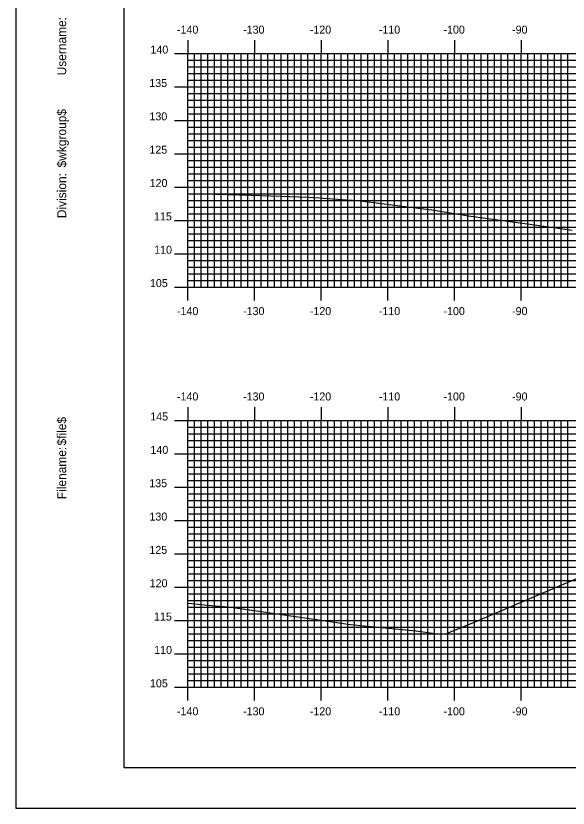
# Model space of a CAD drawing. Extents: x 852147 to 852490, y 364661 to 364881.
# Drawn here: x 852147 to 852229.8, y 364661.3 to 364780 of the extents above; entities that cross this region are included whole.
import ezdxf

# ---------------------------------------------------------------- set-up
doc = ezdxf.new("R2010")
doc.units = 0
for name, color, linetype in [('BORDER', 7, 'Continuous'), ('H_V ANNOTATION', 7, 'Continuous'), ('MAJOR', 7, 'Continuous'), ('MINOR', 7, 'Continuous'), ('PLOT BOUNDARY', 7, 'Continuous'), ('S_Roadway_Centerline', 7, 'Continuous')]:
    doc.layers.add(name, color=color, linetype=linetype)

msp = doc.modelspace()

# ---------------------------------------------------------------- linework, layer by layer
at = {"layer": 'BORDER'}
msp.add_lwpolyline([(852163.16, 364667.37), (852483.16, 364667.37), (852483.16, 364877.37), (852163.16, 364877.37)], close=True, dxfattribs=at)
at = {"layer": 'MAJOR'}
for p, q in [((852172.76, 364776.37), (852172.76, 364774.37)), ((852182.76, 364776.37), (852182.76, 364774.37)), ((852192.76, 364776.37), (852192.76, 364774.37)), ((852202.76, 364776.37), (852202.76, 364774.37)), ((852212.76, 364776.37), (852212.76, 364774.37)), ((852222.76, 364776.37), (852222.76, 364774.37)), ((852170.75, 364774.37), (852172.76, 364774.37)), ((852172.76, 364774.37), (852452.76, 364774.37)), ((852172.76, 364739.37), (852172.76, 364774.37)), ((852172.76, 364739.37), (852172.76, 364774.37)), ((852172.76, 364774.37), (852452.76, 364774.37)), ((852182.76, 364739.37), (852182.76, 364774.37)), ((852192.76, 364739.37), (852192.76, 364774.37)), ((852202.76, 364739.37), (852202.76, 364774.37)), ((852212.76, 364739.37), (852212.76, 364774.37)), ((852222.76, 364739.37), (852222.76, 364774.37)), ((852170.75, 364769.37), (852172.76, 364769.37)), ((852172.76, 364769.37), (852452.76, 364769.37)), ((852170.75, 364764.37), (852172.76, 364764.37)), ((852172.76, 364764.37), (852452.76, 364764.37)), ((852170.75, 364759.37), (852172.76, 364759.37)), ((852172.76, 364759.37), (852452.76, 364759.37)), ((852170.75, 364754.37), (852172.76, 364754.37)), ((852172.76, 364754.37), (852452.76, 364754.37)), ((852170.75, 364749.37), (852172.76, 364749.37)), ((852172.76, 364749.37), (852452.76, 364749.37)), ((852170.75, 364744.37), (852172.76, 364744.37)), ((852172.76, 364744.37), (852452.76, 364744.37)), ((852170.75, 364739.37), (852172.76, 364739.37)), ((852172.76, 364739.37), (852452.76, 364739.37)), ((852172.76, 364739.37), (852452.76, 364739.37)), ((852172.76, 364737.37), (852172.76, 364739.37)), ((852182.76, 364737.37), (852182.76, 364739.37)), ((852192.76, 364737.37), (852192.76, 364739.37)), ((852202.76, 364737.37), (852202.76, 364739.37)), ((852212.76, 364737.37), (852212.76, 364739.37)), ((852222.76, 364737.37), (852222.76, 364739.37)), ((852172.76, 364721.37), (852172.76, 364719.37)), ((852182.76, 364721.37), (852182.76, 364719.37)), ((852192.76, 364721.37), (852192.76, 364719.37)), ((852202.76, 364721.37), (852202.76, 364719.37)), ((852212.76, 364721.37), (852212.76, 364719.37)), ((852222.76, 364721.37), (852222.76, 364719.37)), ((852170.75, 364719.37), (852172.76, 364719.37)), ((852172.76, 364719.37), (852452.76, 364719.37)), ((852172.76, 364679.37), (852172.76, 364719.37)), ((852172.76, 364679.37), (852172.76, 364719.37)), ((852172.76, 364719.37), (852452.76, 364719.37)), ((852182.76, 364679.37), (852182.76, 364719.37)), ((852192.76, 364679.37), (852192.76, 364719.37)), ((852202.76, 364679.37), (852202.76, 364719.37)), ((852212.76, 364679.37), (852212.76, 364719.37)), ((852222.76, 364679.37), (852222.76, 364719.37)), ((852170.75, 364714.37), (852172.76, 364714.37)), ((852172.76, 364714.37), (852452.76, 364714.37)), ((852170.75, 364709.37), (852172.76, 364709.37)), ((852172.76, 364709.37), (852452.76, 364709.37)), ((852170.75, 364704.37), (852172.76, 364704.37)), ((852172.76, 364704.37), (852452.76, 364704.37)), ((852170.75, 364699.37), (852172.76, 364699.37)), ((852172.76, 364699.37), (852452.76, 364699.37)), ((852170.75, 364694.37), (852172.76, 364694.37)), ((852172.76, 364694.37), (852452.76, 364694.37)), ((852170.75, 364689.37), (852172.76, 364689.37)), ((852172.76, 364689.37), (852452.76, 364689.37)), ((852170.75, 364684.37), (852172.76, 364684.37)), ((852172.76, 364684.37), (852452.76, 364684.37)), ((852170.75, 364679.37), (852172.76, 364679.37)), ((852172.76, 364679.37), (852452.76, 364679.37)), ((852172.76, 364679.37), (852452.76, 364679.37)), ((852172.76, 364677.37), (852172.76, 364679.37)), ((852182.76, 364677.37), (852182.76, 364679.37)), ((852192.76, 364677.37), (852192.76, 364679.37)), ((852202.76, 364677.37), (852202.76, 364679.37)), ((852212.76, 364677.37), (852212.76, 364679.37)), ((852222.76, 364677.37), (852222.76, 364679.37))]:
    msp.add_line(p, q, dxfattribs=at)
at = {"layer": 'MINOR'}
for p, q in [((852173.76, 364739.37), (852173.76, 364774.37)), ((852174.76, 364739.37), (852174.76, 364774.37)), ((852175.76, 364739.37), (852175.76, 364774.37)), ((852176.76, 364739.37), (852176.76, 364774.37)), ((852177.76, 364739.37), (852177.76, 364774.37)), ((852178.76, 364739.37), (852178.76, 364774.37)), ((852179.76, 364739.37), (852179.76, 364774.37)), ((852180.76, 364739.37), (852180.76, 364774.37)), ((852181.76, 364739.37), (852181.76, 364774.37)), ((852183.76, 364739.37), (852183.76, 364774.37)), ((852184.76, 364739.37), (852184.76, 364774.37)), ((852185.76, 364739.37), (852185.76, 364774.37)), ((852186.76, 364739.37), (852186.76, 364774.37)), ((852187.76, 364739.37), (852187.76, 364774.37)), ((852188.76, 364739.37), (852188.76, 364774.37)), ((852189.76, 364739.37), (852189.76, 364774.37)), ((852190.76, 364739.37), (852190.76, 364774.37)), ((852191.76, 364739.37), (852191.76, 364774.37)), ((852193.76, 364739.37), (852193.76, 364774.37)), ((852194.76, 364739.37), (852194.76, 364774.37)), ((852195.76, 364739.37), (852195.76, 364774.37)), ((852196.76, 364739.37), (852196.76, 364774.37)), ((852197.76, 364739.37), (852197.76, 364774.37)), ((852198.76, 364739.37), (852198.76, 364774.37)), ((852199.76, 364739.37), (852199.76, 364774.37)), ((852200.76, 364739.37), (852200.76, 364774.37)), ((852201.76, 364739.37), (852201.76, 364774.37)), ((852203.76, 364739.37), (852203.76, 364774.37)), ((852204.76, 364739.37), (852204.76, 364774.37)), ((852205.76, 364739.37), (852205.76, 364774.37)), ((852206.76, 364739.37), (852206.76, 364774.37)), ((852207.76, 364739.37), (852207.76, 364774.37)), ((852208.76, 364739.37), (852208.76, 364774.37)), ((852209.76, 364739.37), (852209.76, 364774.37)), ((852210.76, 364739.37), (852210.76, 364774.37)), ((852211.76, 364739.37), (852211.76, 364774.37)), ((852213.76, 364739.37), (852213.76, 364774.37)), ((852214.76, 364739.37), (852214.76, 364774.37)), ((852215.76, 364739.37), (852215.76, 364774.37)), ((852216.76, 364739.37), (852216.76, 364774.37)), ((852217.76, 364739.37), (852217.76, 364774.37)), ((852218.76, 364739.37), (852218.76, 364774.37)), ((852219.76, 364739.37), (852219.76, 364774.37)), ((852220.76, 364739.37), (852220.76, 364774.37)), ((852221.76, 364739.37), (852221.76, 364774.37)), ((852223.76, 364739.37), (852223.76, 364774.37)), ((852224.76, 364739.37), (852224.76, 364774.37)), ((852225.76, 364739.37), (852225.76, 364774.37)), ((852226.76, 364739.37), (852226.76, 364774.37)), ((852227.76, 364739.37), (852227.76, 364774.37)), ((852228.76, 364739.37), (852228.76, 364774.37)), ((852229.76, 364739.37), (852229.76, 364774.37)), ((852172.76, 364773.37), (852452.76, 364773.37)), ((852172.76, 364773.37), (852174.76, 364773.37)), ((852172.76, 364772.37), (852452.76, 364772.37)), ((852172.76, 364772.37), (852174.76, 364772.37)), ((852172.76, 364771.37), (852452.76, 364771.37)), ((852172.76, 364771.37), (852174.76, 364771.37)), ((852172.76, 364770.37), (852452.76, 364770.37)), ((852172.76, 364770.37), (852174.76, 364770.37)), ((852172.76, 364768.37), (852452.76, 364768.37)), ((852172.76, 364768.37), (852174.76, 364768.37)), ((852172.76, 364767.37), (852452.76, 364767.37)), ((852172.76, 364767.37), (852174.76, 364767.37)), ((852172.76, 364766.37), (852452.76, 364766.37)), ((852172.76, 364766.37), (852174.76, 364766.37)), ((852172.76, 364765.37), (852452.76, 364765.37)), ((852172.76, 364765.37), (852174.76, 364765.37)), ((852172.76, 364763.37), (852452.76, 364763.37)), ((852172.76, 364763.37), (852174.76, 364763.37)), ((852172.76, 364762.37), (852452.76, 364762.37)), ((852172.76, 364762.37), (852174.76, 364762.37)), ((852172.76, 364761.37), (852452.76, 364761.37)), ((852172.76, 364761.37), (852174.76, 364761.37)), ((852172.76, 364760.37), (852452.76, 364760.37)), ((852172.76, 364760.37), (852174.76, 364760.37)), ((852172.76, 364758.37), (852452.76, 364758.37)), ((852172.76, 364758.37), (852174.76, 364758.37)), ((852172.76, 364757.37), (852452.76, 364757.37)), ((852172.76, 364757.37), (852174.76, 364757.37)), ((852172.76, 364756.37), (852452.76, 364756.37)), ((852172.76, 364756.37), (852174.76, 364756.37)), ((852172.76, 364755.37), (852452.76, 364755.37)), ((852172.76, 364755.37), (852174.76, 364755.37)), ((852172.76, 364753.37), (852452.76, 364753.37)), ((852172.76, 364753.37), (852174.76, 364753.37)), ((852172.76, 364752.37), (852452.76, 364752.37)), ((852172.76, 364752.37), (852174.76, 364752.37)), ((852172.76, 364751.37), (852452.76, 364751.37)), ((852172.76, 364751.37), (852174.76, 364751.37)), ((852172.76, 364750.37), (852452.76, 364750.37)), ((852172.76, 364750.37), (852174.76, 364750.37)), ((852172.76, 364748.37), (852452.76, 364748.37)), ((852172.76, 364748.37), (852174.76, 364748.37)), ((852172.76, 364747.37), (852452.76, 364747.37)), ((852172.76, 364747.37), (852174.76, 364747.37)), ((852172.76, 364746.37), (852452.76, 364746.37)), ((852172.76, 364746.37), (852174.76, 364746.37)), ((852172.76, 364745.37), (852452.76, 364745.37)), ((852172.76, 364745.37), (852174.76, 364745.37)), ((852172.76, 364743.37), (852452.76, 364743.37)), ((852172.76, 364743.37), (852174.76, 364743.37)), ((852172.76, 364742.37), (852452.76, 364742.37)), ((852172.76, 364742.37), (852174.76, 364742.37)), ((852172.76, 364741.37), (852452.76, 364741.37)), ((852172.76, 364741.37), (852174.76, 364741.37)), ((852172.76, 364740.37), (852452.76, 364740.37)), ((852172.76, 364740.37), (852174.76, 364740.37)), ((852172.76, 364718.37), (852452.76, 364718.37)), ((852172.76, 364718.37), (852174.76, 364718.37)), ((852173.76, 364679.37), (852173.76, 364719.37)), ((852174.76, 364679.37), (852174.76, 364719.37)), ((852175.76, 364679.37), (852175.76, 364719.37)), ((852176.76, 364679.37), (852176.76, 364719.37)), ((852177.76, 364679.37), (852177.76, 364719.37)), ((852178.76, 364679.37), (852178.76, 364719.37)), ((852179.76, 364679.37), (852179.76, 364719.37)), ((852180.76, 364679.37), (852180.76, 364719.37)), ((852181.76, 364679.37), (852181.76, 364719.37)), ((852183.76, 364679.37), (852183.76, 364719.37)), ((852184.76, 364679.37), (852184.76, 364719.37)), ((852185.76, 364679.37), (852185.76, 364719.37)), ((852186.76, 364679.37), (852186.76, 364719.37)), ((852187.76, 364679.37), (852187.76, 364719.37)), ((852188.76, 364679.37), (852188.76, 364719.37)), ((852189.76, 364679.37), (852189.76, 364719.37)), ((852190.76, 364679.37), (852190.76, 364719.37)), ((852191.76, 364679.37), (852191.76, 364719.37)), ((852193.76, 364679.37), (852193.76, 364719.37)), ((852194.76, 364679.37), (852194.76, 364719.37)), ((852195.76, 364679.37), (852195.76, 364719.37)), ((852196.76, 364679.37), (852196.76, 364719.37)), ((852197.76, 364679.37), (852197.76, 364719.37)), ((852198.76, 364679.37), (852198.76, 364719.37)), ((852199.76, 364679.37), (852199.76, 364719.37)), ((852200.76, 364679.37), (852200.76, 364719.37)), ((852201.76, 364679.37), (852201.76, 364719.37)), ((852203.76, 364679.37), (852203.76, 364719.37)), ((852204.76, 364679.37), (852204.76, 364719.37)), ((852205.76, 364679.37), (852205.76, 364719.37)), ((852206.76, 364679.37), (852206.76, 364719.37)), ((852207.76, 364679.37), (852207.76, 364719.37)), ((852208.76, 364679.37), (852208.76, 364719.37)), ((852209.76, 364679.37), (852209.76, 364719.37)), ((852210.76, 364679.37), (852210.76, 364719.37)), ((852211.76, 364679.37), (852211.76, 364719.37)), ((852213.76, 364679.37), (852213.76, 364719.37)), ((852214.76, 364679.37), (852214.76, 364719.37)), ((852215.76, 364679.37), (852215.76, 364719.37)), ((852216.76, 364679.37), (852216.76, 364719.37)), ((852217.76, 364679.37), (852217.76, 364719.37)), ((852218.76, 364679.37), (852218.76, 364719.37)), ((852219.76, 364679.37), (852219.76, 364719.37)), ((852220.76, 364679.37), (852220.76, 364719.37)), ((852221.76, 364679.37), (852221.76, 364719.37)), ((852223.76, 364679.37), (852223.76, 364719.37)), ((852224.76, 364679.37), (852224.76, 364719.37)), ((852225.76, 364679.37), (852225.76, 364719.37)), ((852226.76, 364679.37), (852226.76, 364719.37)), ((852227.76, 364679.37), (852227.76, 364719.37)), ((852228.76, 364679.37), (852228.76, 364719.37)), ((852229.76, 364679.37), (852229.76, 364719.37)), ((852172.76, 364717.37), (852452.76, 364717.37)), ((852172.76, 364717.37), (852174.76, 364717.37)), ((852172.76, 364716.37), (852452.76, 364716.37)), ((852172.76, 364716.37), (852174.76, 364716.37)), ((852172.76, 364715.37), (852452.76, 364715.37)), ((852172.76, 364715.37), (852174.76, 364715.37)), ((852172.76, 364713.37), (852452.76, 364713.37)), ((852172.76, 364713.37), (852174.76, 364713.37)), ((852172.76, 364712.37), (852452.76, 364712.37)), ((852172.76, 364712.37), (852174.76, 364712.37)), ((852172.76, 364711.37), (852452.76, 364711.37)), ((852172.76, 364711.37), (852174.76, 364711.37)), ((852172.76, 364710.37), (852452.76, 364710.37)), ((852172.76, 364710.37), (852174.76, 364710.37)), ((852172.76, 364708.37), (852452.76, 364708.37)), ((852172.76, 364708.37), (852174.76, 364708.37)), ((852172.76, 364707.37), (852452.76, 364707.37)), ((852172.76, 364707.37), (852174.76, 364707.37)), ((852172.76, 364706.37), (852452.76, 364706.37)), ((852172.76, 364706.37), (852174.76, 364706.37)), ((852172.76, 364705.37), (852452.76, 364705.37)), ((852172.76, 364705.37), (852174.76, 364705.37)), ((852172.76, 364703.37), (852452.76, 364703.37)), ((852172.76, 364703.37), (852174.76, 364703.37)), ((852172.76, 364702.37), (852452.76, 364702.37)), ((852172.76, 364702.37), (852174.76, 364702.37)), ((852172.76, 364701.37), (852452.76, 364701.37)), ((852172.76, 364701.37), (852174.76, 364701.37)), ((852172.76, 364700.37), (852452.76, 364700.37)), ((852172.76, 364700.37), (852174.76, 364700.37)), ((852172.76, 364698.37), (852452.76, 364698.37)), ((852172.76, 364698.37), (852174.76, 364698.37)), ((852172.76, 364697.37), (852452.76, 364697.37)), ((852172.76, 364697.37), (852174.76, 364697.37)), ((852172.76, 364696.37), (852452.76, 364696.37)), ((852172.76, 364696.37), (852174.76, 364696.37)), ((852172.76, 364695.37), (852452.76, 364695.37)), ((852172.76, 364695.37), (852174.76, 364695.37)), ((852172.76, 364693.37), (852452.76, 364693.37)), ((852172.76, 364693.37), (852174.76, 364693.37)), ((852172.76, 364692.37), (852452.76, 364692.37)), ((852172.76, 364692.37), (852174.76, 364692.37)), ((852172.76, 364691.37), (852452.76, 364691.37)), ((852172.76, 364691.37), (852174.76, 364691.37)), ((852172.76, 364690.37), (852452.76, 364690.37)), ((852172.76, 364690.37), (852174.76, 364690.37)), ((852172.76, 364688.37), (852452.76, 364688.37)), ((852172.76, 364688.37), (852174.76, 364688.37)), ((852172.76, 364687.37), (852452.76, 364687.37)), ((852172.76, 364687.37), (852174.76, 364687.37)), ((852172.76, 364686.37), (852452.76, 364686.37)), ((852172.76, 364686.37), (852174.76, 364686.37)), ((852172.76, 364685.37), (852452.76, 364685.37)), ((852172.76, 364685.37), (852174.76, 364685.37)), ((852172.76, 364683.37), (852452.76, 364683.37)), ((852172.76, 364683.37), (852174.76, 364683.37)), ((852172.76, 364682.37), (852452.76, 364682.37)), ((852172.76, 364682.37), (852174.76, 364682.37)), ((852172.76, 364681.37), (852452.76, 364681.37)), ((852172.76, 364681.37), (852174.76, 364681.37)), ((852172.76, 364680.37), (852452.76, 364680.37)), ((852172.76, 364680.37), (852174.76, 364680.37))]:
    msp.add_line(p, q, dxfattribs=at)
at = {"layer": 'PLOT BOUNDARY'}
msp.add_lwpolyline([(852146.97, 364661.25), (852486.97, 364661.25), (852486.97, 364881.25), (852146.97, 364881.25)], close=True, dxfattribs=at)
at = {"layer": 'S_Roadway_Centerline'}
for points in [[(852172.76, 364753.37), (852176.9, 364753.29), (852182.27, 364753.16), (852190.92, 364752.83), (852192.66, 364752.75), (852193.01, 364752.72), (852195.23, 364752.57), (852198.23, 364752.33), (852209.38, 364750.96), (852214.87, 364750.07), (852224.08, 364748.8), (852230.42, 364747.89)], [(852172.76, 364691.99), (852173.35, 364691.92), (852175.7, 364691.7), (852179.22, 364691.36), (852183.77, 364690.75), (852197.18, 364688.8), (852207.01, 364687.83), (852210.2, 364687.41), (852211.42, 364687.35), (852211.82, 364687.52), (852215.87, 364689.21), (852228.88, 364694.73), (852235.14, 364697.36)]]:
    msp.add_lwpolyline(points, dxfattribs=at)

# ---------------------------------------------------------------- texts
at = {"layer": 'BORDER'}
for s, p in [('Username:', (852154.52, 364771.11)), ('$wkgroup$', (852154.52, 364757.31)), ('Division:', (852154.52, 364749.7)), ('$file$', (852154.52, 364715.62)), ('Filename:', (852154.52, 364707.57))]:
    msp.add_text(s, height=1.339, rotation=90, dxfattribs=at).set_placement(p)
at = {"layer": 'H_V ANNOTATION'}
for s, p in [('-140', (852171.14, 364777.37)), ('-130', (852181.06, 364777.37)), ('-120', (852191.07, 364777.37)), ('-110', (852201.42, 364777.37)), ('-100', (852211.12, 364777.37)), ('-90', (852221.41, 364777.37)), ('140', (852167.16, 364774.37)), ('135', (852166.98, 364769.37)), ('130', (852167.01, 364764.37)), ('125', (852167, 364759.37)), ('120', (852167.04, 364754.37)), ('115', (852167.69, 364749.37)), ('110', (852167.72, 364744.37)), ('105', (852167.09, 364739.37)), ('-140', (852171.14, 364735.17)), ('-130', (852181.06, 364735.17)), ('-120', (852191.07, 364735.17)), ('-110', (852201.42, 364735.17)), ('-100', (852211.12, 364735.17)), ('-90', (852221.41, 364735.17)), ('-140', (852171.14, 364722.37)), ('-130', (852181.06, 364722.37)), ('-120', (852191.07, 364722.37)), ('-110', (852201.42, 364722.37)), ('-100', (852211.12, 364722.37)), ('-90', (852221.41, 364722.37)), ('145', (852167.13, 364719.37)), ('140', (852167.16, 364714.37)), ('135', (852166.98, 364709.37)), ('130', (852167.01, 364704.37)), ('125', (852167, 364699.37)), ('120', (852167.04, 364694.37)), ('115', (852167.69, 364689.37)), ('110', (852167.72, 364684.37)), ('105', (852167.09, 364679.37)), ('-140', (852171.14, 364675.17)), ('-130', (852181.06, 364675.17)), ('-120', (852191.07, 364675.17)), ('-110', (852201.42, 364675.17)), ('-100', (852211.12, 364675.17)), ('-90', (852221.41, 364675.17))]:
    msp.add_text(s, height=1.2, dxfattribs=at).set_placement(p)
at = {"layer": 'MAJOR'}
for p in [(852172.75, 364739.37), (852172.75, 364679.37)]:
    msp.add_text('-', height=0.012, dxfattribs=at).set_placement(p)

doc.saveas('drawing.dxf')
